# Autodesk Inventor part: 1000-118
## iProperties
Created: 2007-03
Part Number: 1000-118
Document SubType Name: Modeling
Designer: Andy Moles
Material: Steel
Mass: 84.1056 g
Surface Area: 77.35 cm^2
Volume: 10.7141 cm^3
Density: 7.85 g/cm^3
Author: Andy Moles
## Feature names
1. Base1
